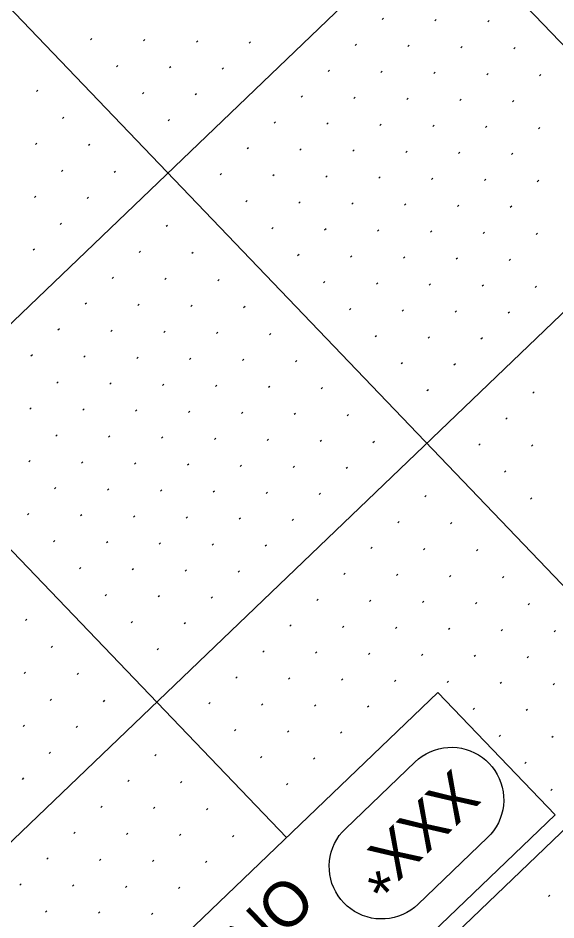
# Model space of a CAD drawing. Extents: x 2148987 to 2151117, y 142806 to 144993.
# Drawn here: x 2149953.1 to 2150025.1, y 143892.2 to 144012.7 of the extents above; entities that cross this region are included whole.
import ezdxf

# ---------------------------------------------------------------- set-up
doc = ezdxf.new("R2010")
doc.units = 0
for name, color, linetype in [('PR_Grading_Txt', 7, 'Continuous'), ('PR_Misc_Improvement', 7, 'Continuous'), ('PR_PIER_PH3', 7, 'Continuous'), ('PR_Storm_Txt_PH1B', 7, 'Continuous'), ('SHT_Profile_Grid_Minor', 7, 'Continuous')]:
    doc.layers.add(name, color=color, linetype=linetype)

msp = doc.modelspace()

# ---------------------------------------------------------------- linework, layer by layer
at = {"layer": 'PR_Misc_Improvement'}
msp.add_lwpolyline([(2150024.95, 143906.21), (2149912.27, 143798.22), (2149896.58, 143814.59), (2150009.26, 143922.58)], close=True, dxfattribs=at)
at = {"layer": 'PR_PIER_PH3'}
for p, q in [((2150469.54, 144467.67), (2149332.4, 143377.92)), ((2150504.13, 144431.57), (2149367, 143341.82)), ((2150538.73, 144395.47), (2149401.59, 143305.72)), ((2149767.1, 144279.28), (2150113.05, 143918.28)), ((2149731, 144244.68), (2150076.96, 143883.69)), ((2149694.9, 144210.09), (2149989.02, 143903.18))]:
    msp.add_line(p, q, dxfattribs=at)
at = {"layer": 'PR_Storm_Txt_PH1B'}
for points in [[(2150006.24, 143913.3), (2150006.7, 143913.71), (2150007.19, 143914.07), (2150007.71, 143914.39), (2150008.26, 143914.66), (2150008.83, 143914.88), (2150009.41, 143915.05), (2150010.01, 143915.17), (2150010.62, 143915.23), (2150011.23, 143915.25), (2150011.84, 143915.21), (2150012.44, 143915.12), (2150013.04, 143914.97), (2150013.61, 143914.78), (2150014.17, 143914.53), (2150014.71, 143914.24), (2150015.22, 143913.9), (2150015.69, 143913.52), (2150016.13, 143913.09), (2150016.13, 143913.09), (2150016.54, 143912.63), (2150016.9, 143912.14), (2150017.22, 143911.62), (2150017.49, 143911.07), (2150017.71, 143910.5), (2150017.88, 143909.92), (2150018, 143909.32), (2150018.07, 143908.71), (2150018.08, 143908.1), (2150018.04, 143907.49), (2150017.95, 143906.89), (2150017.8, 143906.29), (2150017.61, 143905.72), (2150017.36, 143905.16), (2150017.07, 143904.62), (2150016.73, 143904.11), (2150016.35, 143903.64), (2150015.92, 143903.2)], [(2149996.91, 143904.36), (2150006.24, 143913.3)], [(2150006.6, 143894.26), (2150006.14, 143893.85), (2150005.64, 143893.49), (2150005.12, 143893.17), (2150004.57, 143892.9), (2150004.01, 143892.68), (2150003.42, 143892.51), (2150002.82, 143892.39), (2150002.21, 143892.32), (2150001.6, 143892.31), (2150000.99, 143892.35), (2150000.39, 143892.44), (2149999.8, 143892.59), (2149999.22, 143892.78), (2149998.66, 143893.03), (2149998.12, 143893.32), (2149997.62, 143893.66), (2149997.14, 143894.04), (2149996.7, 143894.47), (2149996.7, 143894.47), (2149996.3, 143894.93), (2149995.93, 143895.42), (2149995.62, 143895.94), (2149995.35, 143896.49), (2149995.12, 143897.06), (2149994.95, 143897.64), (2149994.83, 143898.24), (2149994.77, 143898.85), (2149994.75, 143899.46), (2149994.79, 143900.07), (2149994.89, 143900.67), (2149995.03, 143901.26), (2149995.23, 143901.84), (2149995.47, 143902.4), (2149995.77, 143902.94), (2149996.1, 143903.45), (2149996.49, 143903.92), (2149996.91, 143904.36)], [(2150015.92, 143903.2), (2150006.6, 143894.26)]]:
    msp.add_lwpolyline(points, dxfattribs=at)
at = {"layer": 'SHT_Profile_Grid_Minor'}
for p, q in [((2150001.99, 144012.68), (2150001.81, 144012.5)), ((2150009.06, 144012.53), (2150008.88, 144012.35)), ((2150016.13, 144012.38), (2150015.95, 144012.2)), ((2149963.03, 144009.97), (2149962.85, 144009.8)), ((2149970.1, 144009.82), (2149969.92, 144009.65)), ((2149977.17, 144009.67), (2149976.99, 144009.5)), ((2149984.24, 144009.52), (2149984.06, 144009.35)), ((2149998.38, 144009.22), (2149998.2, 144009.04)), ((2150005.45, 144009.07), (2150005.27, 144008.89)), ((2150012.52, 144008.92), (2150012.34, 144008.74)), ((2150019.59, 144008.77), (2150019.41, 144008.59)), ((2149966.49, 144006.36), (2149966.31, 144006.19)), ((2149973.56, 144006.21), (2149973.38, 144006.04)), ((2149980.63, 144006.06), (2149980.45, 144005.89)), ((2149994.77, 144005.76), (2149994.59, 144005.58)), ((2150001.84, 144005.61), (2150001.66, 144005.43)), ((2150008.91, 144005.46), (2150008.73, 144005.28)), ((2150015.98, 144005.31), (2150015.8, 144005.13)), ((2150023.05, 144005.16), (2150022.87, 144004.98)), ((2149955.81, 144003.05), (2149955.63, 144002.88)), ((2149969.95, 144002.75), (2149969.77, 144002.58)), ((2149977.02, 144002.6), (2149976.84, 144002.43)), ((2149991.16, 144002.3), (2149990.98, 144002.13)), ((2149998.23, 144002.15), (2149998.05, 144001.97)), ((2150005.3, 144002), (2150005.12, 144001.82)), ((2150012.37, 144001.85), (2150012.19, 144001.67)), ((2150019.44, 144001.7), (2150019.26, 144001.52)), ((2149959.27, 143999.44), (2149959.09, 143999.27)), ((2149973.41, 143999.14), (2149973.23, 143998.97)), ((2149987.55, 143998.84), (2149987.37, 143998.67)), ((2149994.62, 143998.69), (2149994.44, 143998.52)), ((2150001.69, 143998.54), (2150001.51, 143998.36)), ((2150008.76, 143998.39), (2150008.58, 143998.21)), ((2150015.83, 143998.24), (2150015.65, 143998.06)), ((2150022.9, 143998.09), (2150022.72, 143997.91)), ((2149955.66, 143995.98), (2149955.48, 143995.81)), ((2149962.73, 143995.83), (2149962.55, 143995.66)), ((2149983.94, 143995.38), (2149983.76, 143995.21)), ((2149991.01, 143995.23), (2149990.83, 143995.06)), ((2149998.08, 143995.08), (2149997.9, 143994.91)), ((2150005.15, 143994.93), (2150004.97, 143994.76)), ((2150012.22, 143994.78), (2150012.04, 143994.6)), ((2150019.29, 143994.63), (2150019.11, 143994.45)), ((2149959.12, 143992.37), (2149958.94, 143992.2)), ((2149966.19, 143992.22), (2149966.01, 143992.05)), ((2149980.33, 143991.92), (2149980.15, 143991.75)), ((2149987.4, 143991.77), (2149987.22, 143991.6)), ((2149994.47, 143991.62), (2149994.29, 143991.45)), ((2150001.54, 143991.47), (2150001.36, 143991.3)), ((2150008.61, 143991.32), (2150008.43, 143991.15)), ((2150015.68, 143991.17), (2150015.5, 143990.99)), ((2150022.75, 143991.02), (2150022.57, 143990.84)), ((2149955.51, 143988.91), (2149955.33, 143988.74)), ((2149962.58, 143988.76), (2149962.4, 143988.59)), ((2149983.79, 143988.31), (2149983.61, 143988.14)), ((2149990.86, 143988.16), (2149990.68, 143987.99)), ((2149997.93, 143988.01), (2149997.75, 143987.84)), ((2150005, 143987.86), (2150004.82, 143987.69)), ((2150012.07, 143987.71), (2150011.89, 143987.54)), ((2150019.14, 143987.56), (2150018.96, 143987.38)), ((2149958.97, 143985.3), (2149958.79, 143985.13)), ((2149973.11, 143985), (2149972.93, 143984.83)), ((2149987.25, 143984.7), (2149987.07, 143984.53)), ((2149994.32, 143984.55), (2149994.14, 143984.38)), ((2150001.39, 143984.4), (2150001.21, 143984.23)), ((2150008.46, 143984.25), (2150008.28, 143984.08)), ((2150015.53, 143984.1), (2150015.35, 143983.93)), ((2150022.6, 143983.95), (2150022.42, 143983.77)), ((2149955.36, 143981.84), (2149955.18, 143981.67)), ((2149969.5, 143981.54), (2149969.32, 143981.37)), ((2149976.57, 143981.39), (2149976.39, 143981.22)), ((2149990.71, 143981.09), (2149990.53, 143980.92)), ((2149997.78, 143980.94), (2149997.6, 143980.77)), ((2150004.85, 143980.79), (2150004.67, 143980.62)), ((2150011.92, 143980.64), (2150011.74, 143980.47)), ((2150018.99, 143980.49), (2150018.81, 143980.32)), ((2149965.89, 143978.08), (2149965.71, 143977.91)), ((2149972.96, 143977.93), (2149972.78, 143977.76)), ((2149980.03, 143977.78), (2149979.85, 143977.61)), ((2149994.17, 143977.48), (2149993.99, 143977.31)), ((2150001.24, 143977.33), (2150001.06, 143977.16)), ((2150008.31, 143977.18), (2150008.13, 143977.01)), ((2150015.38, 143977.03), (2150015.2, 143976.86)), ((2150022.45, 143976.88), (2150022.26, 143976.71)), ((2149962.28, 143974.62), (2149962.1, 143974.45)), ((2149969.35, 143974.47), (2149969.17, 143974.3)), ((2149976.42, 143974.32), (2149976.24, 143974.15)), ((2149983.49, 143974.17), (2149983.31, 143974)), ((2149997.63, 143973.87), (2149997.45, 143973.7)), ((2150004.7, 143973.72), (2150004.52, 143973.55)), ((2150011.77, 143973.57), (2150011.59, 143973.4)), ((2150018.84, 143973.42), (2150018.65, 143973.25)), ((2149958.67, 143971.16), (2149958.49, 143970.99)), ((2149965.74, 143971.01), (2149965.56, 143970.84)), ((2149972.81, 143970.86), (2149972.63, 143970.69)), ((2149979.88, 143970.71), (2149979.7, 143970.54)), ((2149986.95, 143970.56), (2149986.77, 143970.39)), ((2150001.09, 143970.26), (2150000.91, 143970.09)), ((2150008.16, 143970.11), (2150007.98, 143969.94)), ((2150015.23, 143969.96), (2150015.04, 143969.79)), ((2149955.06, 143967.7), (2149954.88, 143967.53)), ((2149962.13, 143967.55), (2149961.95, 143967.38)), ((2149969.2, 143967.4), (2149969.02, 143967.23)), ((2149976.27, 143967.25), (2149976.09, 143967.08)), ((2149983.34, 143967.1), (2149983.16, 143966.93)), ((2149990.41, 143966.95), (2149990.23, 143966.78)), ((2150004.55, 143966.65), (2150004.37, 143966.48)), ((2150011.62, 143966.5), (2150011.43, 143966.33)), ((2149958.52, 143964.09), (2149958.34, 143963.92)), ((2149965.59, 143963.94), (2149965.41, 143963.77)), ((2149972.66, 143963.79), (2149972.48, 143963.62)), ((2149979.73, 143963.64), (2149979.55, 143963.47)), ((2149986.8, 143963.49), (2149986.62, 143963.32)), ((2149993.87, 143963.34), (2149993.69, 143963.17)), ((2150008.01, 143963.04), (2150007.82, 143962.87)), ((2150022.14, 143962.74), (2150021.96, 143962.57)), ((2149954.91, 143960.63), (2149954.73, 143960.46)), ((2149961.98, 143960.48), (2149961.8, 143960.31)), ((2149969.05, 143960.33), (2149968.87, 143960.16)), ((2149976.12, 143960.18), (2149975.94, 143960.01)), ((2149983.19, 143960.03), (2149983.01, 143959.86)), ((2149990.26, 143959.88), (2149990.08, 143959.71)), ((2149997.33, 143959.73), (2149997.15, 143959.56)), ((2150018.53, 143959.28), (2150018.35, 143959.11)), ((2149958.37, 143957.02), (2149958.19, 143956.85)), ((2149965.44, 143956.87), (2149965.26, 143956.7)), ((2149972.51, 143956.72), (2149972.33, 143956.55)), ((2149979.58, 143956.57), (2149979.4, 143956.4)), ((2149986.65, 143956.42), (2149986.47, 143956.25)), ((2149993.72, 143956.27), (2149993.54, 143956.1)), ((2150000.79, 143956.12), (2150000.6, 143955.95)), ((2150014.92, 143955.82), (2150014.74, 143955.65)), ((2150021.99, 143955.67), (2150021.81, 143955.5)), ((2149954.76, 143953.56), (2149954.58, 143953.39)), ((2149961.83, 143953.41), (2149961.65, 143953.24)), ((2149968.9, 143953.26), (2149968.72, 143953.09)), ((2149975.97, 143953.11), (2149975.79, 143952.94)), ((2149983.04, 143952.96), (2149982.86, 143952.79)), ((2149990.11, 143952.81), (2149989.93, 143952.64)), ((2149997.18, 143952.66), (2149997, 143952.49)), ((2150018.38, 143952.21), (2150018.2, 143952.04)), ((2149958.22, 143949.95), (2149958.04, 143949.78)), ((2149965.29, 143949.8), (2149965.11, 143949.63)), ((2149972.36, 143949.65), (2149972.18, 143949.48)), ((2149979.43, 143949.5), (2149979.25, 143949.33)), ((2149986.5, 143949.35), (2149986.32, 143949.18)), ((2149993.57, 143949.2), (2149993.39, 143949.03)), ((2150007.7, 143948.9), (2150007.52, 143948.73)), ((2150021.84, 143948.6), (2150021.66, 143948.43)), ((2149954.61, 143946.49), (2149954.43, 143946.32)), ((2149961.68, 143946.34), (2149961.5, 143946.17)), ((2149968.75, 143946.19), (2149968.57, 143946.02)), ((2149975.82, 143946.04), (2149975.64, 143945.87)), ((2149982.89, 143945.89), (2149982.71, 143945.72)), ((2149989.96, 143945.74), (2149989.78, 143945.57)), ((2150004.09, 143945.44), (2150003.91, 143945.27)), ((2150011.16, 143945.29), (2150010.98, 143945.12)), ((2149958.07, 143942.88), (2149957.89, 143942.71)), ((2149965.14, 143942.73), (2149964.96, 143942.56)), ((2149972.21, 143942.58), (2149972.03, 143942.41)), ((2149979.28, 143942.43), (2149979.1, 143942.26)), ((2149986.35, 143942.28), (2149986.17, 143942.11)), ((2150000.48, 143941.98), (2150000.3, 143941.81)), ((2150007.55, 143941.83), (2150007.37, 143941.66)), ((2150014.62, 143941.68), (2150014.44, 143941.51)), ((2149961.53, 143939.27), (2149961.35, 143939.1)), ((2149968.6, 143939.12), (2149968.42, 143938.95)), ((2149975.67, 143938.97), (2149975.49, 143938.8)), ((2149982.74, 143938.82), (2149982.56, 143938.65)), ((2149996.87, 143938.52), (2149996.69, 143938.35)), ((2150003.94, 143938.37), (2150003.76, 143938.2)), ((2150011.01, 143938.22), (2150010.83, 143938.05)), ((2150018.08, 143938.07), (2150017.9, 143937.9)), ((2149964.99, 143935.66), (2149964.81, 143935.49)), ((2149972.06, 143935.51), (2149971.88, 143935.34)), ((2149979.13, 143935.36), (2149978.95, 143935.19)), ((2149993.26, 143935.06), (2149993.08, 143934.89)), ((2150000.33, 143934.91), (2150000.15, 143934.74)), ((2150007.4, 143934.76), (2150007.22, 143934.59)), ((2150014.47, 143934.61), (2150014.29, 143934.44)), ((2150021.54, 143934.46), (2150021.36, 143934.29)), ((2149954.31, 143932.36), (2149954.13, 143932.18)), ((2149968.45, 143932.06), (2149968.27, 143931.88)), ((2149975.52, 143931.9), (2149975.34, 143931.73)), ((2149989.65, 143931.6), (2149989.47, 143931.43)), ((2149996.72, 143931.45), (2149996.54, 143931.28)), ((2150003.79, 143931.3), (2150003.61, 143931.13)), ((2150010.86, 143931.15), (2150010.68, 143930.98)), ((2150017.93, 143931), (2150017.75, 143930.83)), ((2150025, 143930.85), (2150024.82, 143930.68)), ((2149957.77, 143928.75), (2149957.59, 143928.57)), ((2149971.91, 143928.45), (2149971.73, 143928.27)), ((2149986.04, 143928.14), (2149985.86, 143927.97)), ((2149993.11, 143927.99), (2149992.93, 143927.82)), ((2150000.18, 143927.84), (2150000, 143927.67)), ((2150007.25, 143927.69), (2150007.07, 143927.52)), ((2150014.32, 143927.54), (2150014.14, 143927.37)), ((2150021.39, 143927.39), (2150021.21, 143927.22)), ((2149954.16, 143925.29), (2149953.98, 143925.11)), ((2149961.23, 143925.14), (2149961.05, 143924.96)), ((2149982.43, 143924.68), (2149982.25, 143924.51)), ((2149989.5, 143924.53), (2149989.32, 143924.36)), ((2149996.57, 143924.38), (2149996.39, 143924.21)), ((2150003.64, 143924.23), (2150003.46, 143924.06)), ((2150010.71, 143924.08), (2150010.53, 143923.91)), ((2150017.78, 143923.93), (2150017.6, 143923.76)), ((2150024.85, 143923.78), (2150024.67, 143923.61)), ((2149957.62, 143921.68), (2149957.44, 143921.5)), ((2149964.69, 143921.53), (2149964.51, 143921.35)), ((2149978.82, 143921.23), (2149978.64, 143921.05)), ((2149985.89, 143921.07), (2149985.71, 143920.9)), ((2149992.96, 143920.92), (2149992.78, 143920.75)), ((2150000.03, 143920.77), (2149999.85, 143920.6)), ((2150014.17, 143920.47), (2150013.99, 143920.3)), ((2150021.24, 143920.32), (2150021.06, 143920.15)), ((2149954.01, 143918.22), (2149953.83, 143918.04)), ((2149961.08, 143918.07), (2149960.9, 143917.89)), ((2149982.28, 143917.62), (2149982.1, 143917.44)), ((2149989.35, 143917.46), (2149989.17, 143917.29)), ((2149996.42, 143917.31), (2149996.24, 143917.14)), ((2150017.63, 143916.86), (2150017.45, 143916.69)), ((2150024.7, 143916.71), (2150024.52, 143916.54)), ((2149957.47, 143914.61), (2149957.29, 143914.43)), ((2149971.61, 143914.31), (2149971.42, 143914.13)), ((2149985.74, 143914.01), (2149985.56, 143913.83)), ((2149992.81, 143913.85), (2149992.63, 143913.68)), ((2150021.09, 143913.25), (2150020.91, 143913.08)), ((2149953.86, 143911.15), (2149953.68, 143910.97)), ((2149968, 143910.85), (2149967.81, 143910.67)), ((2149975.06, 143910.7), (2149974.88, 143910.52)), ((2149989.2, 143910.4), (2149989.02, 143910.22)), ((2150024.55, 143909.64), (2150024.37, 143909.47)), ((2149964.39, 143907.39), (2149964.2, 143907.21)), ((2149971.45, 143907.24), (2149971.27, 143907.06)), ((2149978.52, 143907.09), (2149978.34, 143906.91)), ((2149960.78, 143903.93), (2149960.59, 143903.75)), ((2149967.84, 143903.78), (2149967.66, 143903.6)), ((2149974.91, 143903.63), (2149974.73, 143903.45)), ((2149981.98, 143903.48), (2149981.8, 143903.3)), ((2149957.17, 143900.47), (2149956.98, 143900.3)), ((2149964.23, 143900.32), (2149964.05, 143900.14)), ((2149971.3, 143900.17), (2149971.12, 143899.99)), ((2149978.37, 143900.02), (2149978.19, 143899.84)), ((2149953.56, 143897.01), (2149953.37, 143896.84)), ((2149960.62, 143896.86), (2149960.44, 143896.69)), ((2149967.69, 143896.71), (2149967.51, 143896.53)), ((2149974.76, 143896.56), (2149974.58, 143896.38)), ((2150024.25, 143895.5), (2150024.07, 143895.33)), ((2149957.01, 143893.4), (2149956.83, 143893.23)), ((2149964.08, 143893.25), (2149963.9, 143893.08)), ((2149971.15, 143893.1), (2149970.97, 143892.92))]:
    msp.add_line(p, q, dxfattribs=at)

# ---------------------------------------------------------------- texts
at = {"layer": 'PR_Grading_Txt'}
msp.add_text('ON PREVIOUS PHASE', height=6, rotation=223.7809, dxfattribs=at).set_placement((2149989.09, 143898.65))
at = {"layer": 'PR_Storm_Txt_PH1B'}
msp.add_text('XXX*', height=6, rotation=223.7809, dxfattribs=at).set_placement((2150011.2, 143912.52))

doc.saveas('drawing.dxf')
